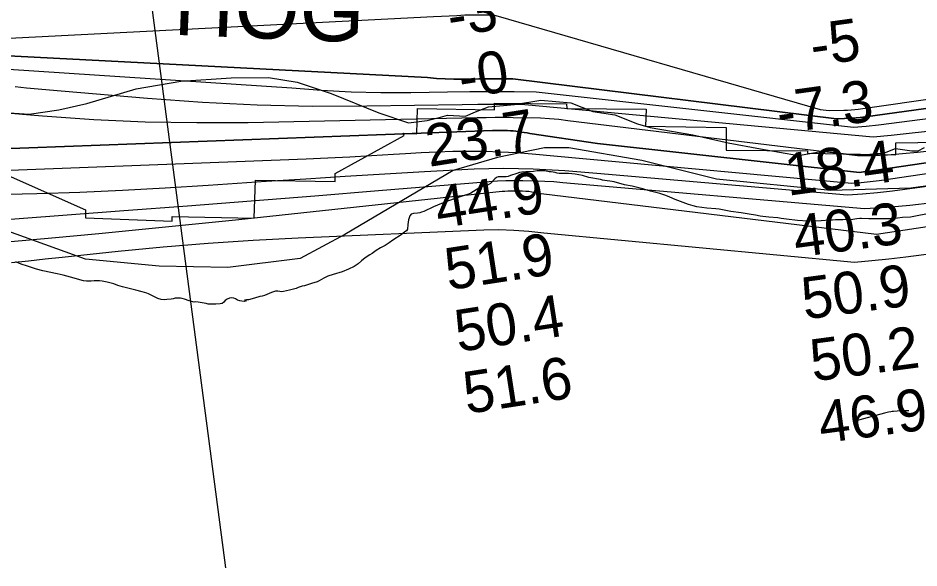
# Model space of a CAD drawing. Extents: x 3192986 to 3230865, y 867483 to 892886.
# Drawn here: x 3202614 to 3204053, y 876187 to 877066 of the extents above; entities that cross this region are included whole.
import ezdxf

# ---------------------------------------------------------------- set-up
doc = ezdxf.new("R2010")
doc.units = 0
for name, color, linetype in [('V-RIVR-EDGE', 7, 'Continuous'), ('V-RIVR-RANG', 7, 'Continuous'), ('V-RRAP-FSHR', 7, 'Continuous'), ('V-RRAP-RVMT', 7, 'Continuous'), ('V-RRAP-RVMT-IDEN', 7, 'Continuous'), ('V-SITE-VEGE', 7, 'Continuous'), ('V-TOPO-DPTH', 7, 'Continuous'), ('V-TOPO-MAJR', 7, 'Continuous'), ('V-TOPO-MINR', 7, 'Continuous'), ('V-TOPO-WATR', 7, 'Continuous')]:
    doc.layers.add(name, color=color, linetype=linetype)

msp = doc.modelspace()

# ---------------------------------------------------------------- linework, layer by layer
at = {"layer": 'V-RIVR-EDGE'}
msp.add_lwpolyline([(3202599.9, 876914.4), (3202631.9, 876912.4), (3202679.1, 876919.4), (3202723.9, 876929.3), (3202802.7, 876953), (3202874.2, 876965.2), (3202954.8, 876970.7), (3203014.5, 876971), (3203060.2, 876963.8), (3203114.1, 876945.5), (3203190.3, 876914.3), (3203237.9, 876898.5), (3203267.5, 876902.2), (3203289, 876907.4), (3203300.4, 876910.7), (3203329, 876909.2), (3203344.8, 876915.9), (3203365.8, 876923.9), (3203407.3, 876928.1), (3203449.3, 876934.7), (3203497, 876930.7), (3203532.2, 876916.8), (3203567.5, 876911.5), (3203603.7, 876897.1), (3203624.2, 876891.3), (3203691.9, 876879.2), (3203748.6, 876866.7), (3203800.1, 876857), (3203861.1, 876846.4), (3203899.7, 876853.5), (3203946, 876848.1), (3203974.6, 876848.5), (3203998.4, 876850.8), (3204015.6, 876857.5), (3204041.8, 876853.6), (3204051.8, 876853.6), (3204062.4, 876859.2)], dxfattribs=at)
at = {"layer": 'V-RIVR-RANG'}
msp.add_line((3202946.1, 876186.9), (3202756, 877634.4), dxfattribs=at)
at = {"layer": 'V-RRAP-FSHR'}
msp.add_lwpolyline([(3204122.5, 876805.2), (3204040.5, 876794), (3203912.8, 876790.2), (3203729.8, 876808.7), (3203610.8, 876838.1), (3203494.1, 876858.4), (3203455.3, 876858.4), (3203380.2, 876842.9), (3203309.4, 876822.1), (3203136.3, 876720), (3203065.1, 876681.8), (3202949.1, 876667.5), (3202839.5, 876669.5), (3202721.9, 876680.7), (3202545.5, 876743.8), (3202438.3, 876819.7), (3202386.2, 876873.5), (3202284.5, 877008.7), (3202190.4, 877075.7), (3202115.3, 877094.8), (3202047.7, 877089.7), (3201993.9, 877081.1), (3201978.5, 877082), (3201950.5, 877081)], dxfattribs=at)
at = {"layer": 'V-RRAP-RVMT'}
for p, q in [((3203375.2, 876919.6), (3203375.1, 876930.1)), ((3203375.1, 876930.1), (3203490.5, 876929)), ((3203490.5, 876929), (3203490.7, 876921.7)), ((3203251.2, 876881.2), (3203252.3, 876921.7)), ((3203252.3, 876921.7), (3203375.2, 876919.6)), ((3203490.7, 876921.7), (3203617.4, 876920.4)), ((3203617.4, 876920.4), (3203616.6, 876893.4)), ((3203616.6, 876893.4), (3203745.5, 876891)), ((3203745.5, 876891), (3203745.2, 876854.8)), ((3203120.8, 876817.4), (3203231.1, 876878.1)), ((3203231.1, 876878.1), (3203229.4, 876881.8)), ((3203229.4, 876881.8), (3203251.2, 876881.2)), ((3204016.2, 876847.6), (3204016.6, 876866.4)), ((3204016.6, 876866.4), (3204144.7, 876868.8)), ((3203745.2, 876854.8), (3203875.5, 876853.8)), ((3203875.5, 876853.8), (3203875.4, 876850.1)), ((3203875.4, 876850.1), (3204016.2, 876847.6)), ((3202598.5, 876814.1), (3202722, 876759.7)), ((3203120.5, 876804.6), (3203120.8, 876817.4)), ((3202991.5, 876746), (3202993.3, 876807.1)), ((3202993.3, 876807.1), (3203120.5, 876804.6)), ((3202722, 876759.7), (3202721.8, 876746.9)), ((3202721.8, 876746.9), (3202860.2, 876741.5)), ((3202860.2, 876741.5), (3202860.5, 876748.9)), ((3202860.5, 876748.9), (3202991.5, 876746))]:
    msp.add_line(p, q, dxfattribs=at)
at = {"layer": 'V-SITE-VEGE'}
for p, q in [((3203397.1, 876813), (3203393.7, 876812.4)), ((3203400.9, 876814.1), (3203397.1, 876813)), ((3203410.8, 876817.7), (3203400.9, 876814.1)), ((3203415.1, 876818.9), (3203410.8, 876817.7)), ((3203419, 876819.7), (3203415.1, 876818.9)), ((3203425.6, 876820.3), (3203419, 876819.7)), ((3203429.3, 876820.3), (3203425.6, 876820.3)), ((3203437.6, 876821), (3203429.3, 876820.3)), ((3203443.2, 876821.9), (3203437.6, 876821)), ((3203451.2, 876822), (3203443.2, 876821.9)), ((3203455.6, 876821.8), (3203451.2, 876822)), ((3203462.7, 876820.4), (3203455.6, 876821.8)), ((3203465.9, 876820.1), (3203462.7, 876820.4)), ((3203469.1, 876819.6), (3203465.9, 876820.1)), ((3203472.3, 876818.9), (3203469.1, 876819.6)), ((3203475.3, 876818), (3203472.3, 876818.9)), ((3203478.5, 876817.6), (3203475.3, 876818)), ((3203482.5, 876817.4), (3203478.5, 876817.6)), ((3203490.4, 876817.8), (3203482.5, 876817.4)), ((3203493.7, 876817.8), (3203490.4, 876817.8)), ((3203504, 876816.7), (3203493.7, 876817.8)), ((3203515.8, 876814.1), (3203504, 876816.7)), ((3203526.2, 876811.2), (3203515.8, 876814.1)), ((3203365.1, 876799.3), (3203361.4, 876798.1)), ((3203368.7, 876801.4), (3203365.1, 876799.3)), ((3203375.7, 876808.9), (3203368.7, 876801.4)), ((3203378.5, 876811), (3203375.7, 876808.9)), ((3203381.4, 876812.1), (3203378.5, 876811)), ((3203385.2, 876812.4), (3203381.4, 876812.1)), ((3203389.5, 876812.2), (3203385.2, 876812.4)), ((3203393.7, 876812.4), (3203389.5, 876812.2)), ((3203544.5, 876807.9), (3203526.2, 876811.2)), ((3203548, 876806.9), (3203544.5, 876807.9)), ((3203551.5, 876806.2), (3203548, 876806.9)), ((3203563.2, 876804.8), (3203551.5, 876806.2)), ((3203566.6, 876804.1), (3203563.2, 876804.8)), ((3203582.8, 876799.6), (3203566.6, 876804.1)), ((3203595, 876797.1), (3203582.8, 876799.6)), ((3203333.7, 876784.5), (3203327, 876782.2)), ((3203337.3, 876786.1), (3203333.7, 876784.5)), ((3203350.1, 876794.3), (3203337.3, 876786.1)), ((3203353.9, 876796.3), (3203350.1, 876794.3)), ((3203361.4, 876798.1), (3203353.9, 876796.3)), ((3203612.3, 876792.8), (3203595, 876797.1)), ((3203616.8, 876791.3), (3203612.3, 876792.8)), ((3203624.5, 876789.2), (3203616.8, 876791.3)), ((3203639.4, 876785.5), (3203624.5, 876789.2)), ((3203649.1, 876782.3), (3203639.4, 876785.5)), ((3203295.8, 876771.6), (3203284.2, 876767.1)), ((3203310.6, 876776.9), (3203295.8, 876771.6)), ((3203320.7, 876780.5), (3203310.6, 876776.9)), ((3203327, 876782.2), (3203320.7, 876780.5)), ((3203655.3, 876779.8), (3203649.1, 876782.3)), ((3203664, 876776), (3203655.3, 876779.8)), ((3203676.4, 876771), (3203664, 876776)), ((3203685.2, 876767.8), (3203676.4, 876771)), ((3203258.9, 876755.5), (3203255.9, 876754.6)), ((3203262.4, 876756.9), (3203258.9, 876755.5)), ((3203277.6, 876764.3), (3203262.4, 876756.9)), ((3203284.2, 876767.1), (3203277.6, 876764.3)), ((3203692.4, 876765.7), (3203685.2, 876767.8)), ((3203698.6, 876764.2), (3203692.4, 876765.7)), ((3203714.7, 876762.2), (3203698.6, 876764.2)), ((3203728.8, 876761.3), (3203714.7, 876762.2)), ((3203734.1, 876760.8), (3203728.8, 876761.3)), ((3203745, 876758.4), (3203734.1, 876760.8)), ((3203752.9, 876757), (3203745, 876758.4)), ((3203769.2, 876754.7), (3203752.9, 876757)), ((3203238, 876743.5), (3203236.7, 876735.8)), ((3203238.8, 876746.7), (3203238, 876743.5)), ((3203240.2, 876749.9), (3203238.8, 876746.7)), ((3203242.2, 876752.4), (3203240.2, 876749.9)), ((3203245.9, 876753.7), (3203242.2, 876752.4)), ((3203252.5, 876754.1), (3203245.9, 876753.7)), ((3203255.9, 876754.6), (3203252.5, 876754.1)), ((3203772.3, 876754.4), (3203769.2, 876754.7)), ((3203778.8, 876753.1), (3203772.3, 876754.4)), ((3203782.1, 876752.8), (3203778.8, 876753.1)), ((3203792, 876751.2), (3203782.1, 876752.8)), ((3203799.6, 876749.5), (3203792, 876751.2)), ((3203803.8, 876748.8), (3203799.6, 876749.5)), ((3203813.6, 876747.7), (3203803.8, 876748.8)), ((3203827.7, 876746.6), (3203813.6, 876747.7)), ((3203833.1, 876745.6), (3203827.7, 876746.6)), ((3203841.9, 876744.7), (3203833.1, 876745.6)), ((3203859.1, 876742.5), (3203841.9, 876744.7)), ((3203875.8, 876741.1), (3203859.1, 876742.5)), ((3203897, 876741.7), (3203875.8, 876741.1)), ((3203910.5, 876743), (3203897, 876741.7)), ((3203915.1, 876743.1), (3203910.5, 876743)), ((3203920, 876743.5), (3203915.1, 876743.1)), ((3203927.1, 876743.7), (3203920, 876743.5)), ((3203931.6, 876743.7), (3203927.1, 876743.7)), ((3203935.2, 876743.9), (3203931.6, 876743.7)), ((3203944.5, 876743.6), (3203935.2, 876743.9)), ((3203953.9, 876744.9), (3203944.5, 876743.6)), ((3203958.8, 876745.4), (3203953.9, 876744.9)), ((3203961.8, 876745.5), (3203958.8, 876745.4)), ((3203973.2, 876745), (3203961.8, 876745.5)), ((3203985, 876745.1), (3203973.2, 876745)), ((3204004.1, 876744.9), (3203985, 876745.1)), ((3204011, 876745.2), (3204004.1, 876744.9)), ((3204027, 876747.1), (3204011, 876745.2)), ((3204039.6, 876748), (3204027, 876747.1)), ((3204048, 876749.3), (3204039.6, 876748)), ((3204067.1, 876753.1), (3204048, 876749.3)), ((3203236.3, 876728.6), (3203234.5, 876726.1)), ((3203236.7, 876735.8), (3203236.3, 876728.6)), ((3203226, 876719.6), (3203212.9, 876711.2)), ((3203231.9, 876724.2), (3203226, 876719.6)), ((3203234.5, 876726.1), (3203231.9, 876724.2)), ((3203193.4, 876698.6), (3203186.4, 876694.2)), ((3203200.4, 876702.6), (3203193.4, 876698.6)), ((3203206.9, 876706.9), (3203200.4, 876702.6)), ((3203212.9, 876711.2), (3203206.9, 876706.9)), ((3203176, 876687.5), (3203168.8, 876682.9)), ((3203179.7, 876689.6), (3203176, 876687.5)), ((3203186.4, 876694.2), (3203179.7, 876689.6)), ((3202616.6, 876673.6), (3202610.8, 876676.2)), ((3202620.8, 876672), (3202616.6, 876673.6)), ((3202627.6, 876670), (3202620.8, 876672)), ((3202635.9, 876667.2), (3202627.6, 876670)), ((3203151, 876669), (3203142.1, 876664.6)), ((3203154.1, 876670.8), (3203151, 876669)), ((3203157.3, 876673.3), (3203154.1, 876670.8)), ((3203162.8, 876678.2), (3203157.3, 876673.3)), ((3203168.8, 876682.9), (3203162.8, 876678.2)), ((3202643.6, 876664.8), (3202635.9, 876667.2)), ((3202654, 876662.1), (3202643.6, 876664.8)), ((3202676.7, 876657.3), (3202654, 876662.1)), ((3202686.1, 876655), (3202676.7, 876657.3)), ((3202697.9, 876651.6), (3202686.1, 876655)), ((3203117.3, 876656.1), (3203109.1, 876653.2)), ((3203131.8, 876660.4), (3203117.3, 876656.1)), ((3203142.1, 876664.6), (3203131.8, 876660.4)), ((3202718.6, 876646.1), (3202697.9, 876651.6)), ((3202723.4, 876645.5), (3202718.6, 876646.1)), ((3202731.1, 876645.5), (3202723.4, 876645.5)), ((3202735.9, 876645.9), (3202731.1, 876645.5)), ((3202744.5, 876645.8), (3202735.9, 876645.9)), ((3202748.7, 876645.6), (3202744.5, 876645.8)), ((3202756.5, 876644), (3202748.7, 876645.6)), ((3202767, 876641), (3202756.5, 876644)), ((3202773.7, 876638.7), (3202767, 876641)), ((3203082.9, 876641.6), (3203071.7, 876638)), ((3203092.1, 876644.6), (3203082.9, 876641.6)), ((3203095, 876645.9), (3203092.1, 876644.6)), ((3203102.4, 876650.1), (3203095, 876645.9)), ((3203105.7, 876651.8), (3203102.4, 876650.1)), ((3203109.1, 876653.2), (3203105.7, 876651.8)), ((3202781.1, 876636.6), (3202773.7, 876638.7)), ((3202802.2, 876631.2), (3202781.1, 876636.6)), ((3202812.6, 876628.4), (3202802.2, 876631.2)), ((3202819.7, 876626.3), (3202812.6, 876628.4)), ((3202822.6, 876625.2), (3202819.7, 876626.3)), ((3203018.8, 876627.3), (3203007.7, 876622.6)), ((3203025.3, 876629.7), (3203018.8, 876627.3)), ((3203029.1, 876629.6), (3203025.3, 876629.7)), ((3203035.3, 876628.4), (3203029.1, 876629.6)), ((3203038.3, 876628.8), (3203035.3, 876628.4)), ((3203047.6, 876631.3), (3203038.3, 876628.8)), ((3203054.3, 876632.6), (3203047.6, 876631.3)), ((3203058.3, 876633.9), (3203054.3, 876632.6)), ((3203061.4, 876635.3), (3203058.3, 876633.9)), ((3203065, 876636.5), (3203061.4, 876635.3)), ((3203068.3, 876637.4), (3203065, 876636.5)), ((3203071.7, 876638), (3203068.3, 876637.4)), ((3202831.9, 876620.5), (3202822.6, 876625.2)), ((3202837.5, 876617.9), (3202831.9, 876620.5)), ((3202842.7, 876616.2), (3202837.5, 876617.9)), ((3202847.7, 876615.6), (3202842.7, 876616.2)), ((3202851.7, 876615.9), (3202847.7, 876615.6)), ((3202859, 876616.7), (3202851.7, 876615.9)), ((3202862.1, 876617.2), (3202859, 876616.7)), ((3202865, 876618), (3202862.1, 876617.2)), ((3202868.5, 876618.3), (3202865, 876618)), ((3202873.6, 876618.2), (3202868.5, 876618.3)), ((3202876.6, 876617.6), (3202873.6, 876618.2)), ((3202880.3, 876616.7), (3202876.6, 876617.6)), ((3202887.6, 876614), (3202880.3, 876616.7)), ((3202895.3, 876611.8), (3202887.6, 876614)), ((3202898.4, 876612.2), (3202895.3, 876611.8)), ((3202901.9, 876612.1), (3202898.4, 876612.2)), ((3202914.5, 876609.6), (3202901.9, 876612.1)), ((3202942.7, 876612), (3202940, 876609.8)), ((3202945.1, 876614.5), (3202942.7, 876612)), ((3202948.4, 876616.4), (3202945.1, 876614.5)), ((3202951.8, 876618), (3202948.4, 876616.4)), ((3202955.1, 876618.7), (3202951.8, 876618)), ((3202958.8, 876618.3), (3202955.1, 876618.7)), ((3202961.8, 876617.1), (3202958.8, 876618.3)), ((3202964.9, 876615.3), (3202961.8, 876617.1)), ((3202968.4, 876613.9), (3202964.9, 876615.3)), ((3202971.6, 876613.2), (3202968.4, 876613.9)), ((3202975.5, 876613), (3202971.6, 876613.2)), ((3202978.8, 876613.8), (3202975.5, 876613)), ((3202979.3, 876615.5), (3202975.9, 876614.8)), ((3202975.9, 876614.8), (3202978.8, 876613.8)), ((3202982.4, 876615.7), (3202979.3, 876615.5)), ((3202992, 876618.2), (3202982.4, 876615.7)), ((3203000.4, 876620.8), (3202992, 876618.2)), ((3203004.3, 876621.4), (3203000.4, 876620.8)), ((3203007.7, 876622.6), (3203004.3, 876621.4)), ((3202918.1, 876608.9), (3202914.5, 876609.6)), ((3202921.6, 876608.5), (3202918.1, 876608.9)), ((3202930.1, 876608.6), (3202921.6, 876608.5)), ((3202936.9, 876609), (3202930.1, 876608.6)), ((3202940, 876609.8), (3202936.9, 876609))]:
    msp.add_line(p, q, dxfattribs=at)
at = {"layer": 'V-TOPO-DPTH'}
for points in [[(3204976.4, 877047.2), (3203971.8, 876908.7), (3203959.3, 876907.2), (3203946.8, 876906.1), (3203934.3, 876905.4), (3203921.7, 876905.1), (3203404.5, 876968.9), (3203386.5, 876969), (3203368.5, 876969), (3203350.5, 876968.8), (3203332.4, 876968.5), (3203324.5, 876968.4), (3203310.4, 876968.3), (3203296.4, 876968.7), (3203282.5, 876969.6), (3203268.5, 876970.9), (3202515.6, 877010.2)], [(3204805.9, 877023.7), (3203971.8, 876908.7), (3203959.3, 876907.2), (3203946.8, 876906.1), (3203934.3, 876905.4), (3203921.7, 876905.1), (3203404.5, 876968.9), (3203386.5, 876969), (3203368.5, 876969), (3203350.5, 876968.8), (3203332.4, 876968.5), (3203324.5, 876968.4), (3203310.4, 876968.3), (3203296.4, 876968.7), (3203282.5, 876969.6), (3203268.5, 876970.9), (3202515.6, 877010.2)], [(3202609.4, 876956.5), (3202627.8, 876954.7), (3202646.2, 876953), (3202664.6, 876951.3), (3202683, 876949.7), (3202821.1, 876937.8), (3202908.6, 876931.6), (3202996.2, 876927.1), (3203083.8, 876925.4), (3203171.5, 876925.5), (3203323.8, 876927.9), (3203348.8, 876928.2), (3203373.8, 876928.3), (3203398.8, 876928.2), (3203423.8, 876927.9), (3203980.3, 876876.3), (3204009.2, 876878.9), (3204172.8, 876896.8)], [(3202609.4, 876956.5), (3202627.8, 876954.7), (3202646.2, 876953), (3202664.6, 876951.3), (3202683, 876949.7), (3202821.1, 876937.8), (3202908.6, 876931.6), (3202996.2, 876927.1), (3203083.8, 876925.4), (3203171.5, 876925.5), (3203323.8, 876927.9), (3203348.8, 876928.2), (3203373.8, 876928.3), (3203398.8, 876928.2), (3203423.8, 876927.9), (3203980.3, 876876.3), (3204009.2, 876878.9), (3204172.8, 876896.8)], [(3204278.3, 876866.2), (3203970.6, 876820.8), (3203964.6, 876820.1), (3203958.6, 876819.4), (3203539.6, 876865.3), (3203431.7, 876881.7), (3203427.3, 876882.4), (3203422.8, 876883), (3203418.4, 876883.8), (3203413.9, 876884.5), (3203409.5, 876885.1), (3203405, 876885.6), (3203400.6, 876885.9), (3203396.1, 876886.1), (3203386.6, 876886.3), (3203383, 876886.3), (3203379.3, 876886.3), (3203375.6, 876886.3), (3203371.9, 876886.2), (3202573.8, 876856.3)]]:
    msp.add_lwpolyline(points, dxfattribs=at)
at = {"layer": 'V-TOPO-MAJR'}
msp.add_lwpolyline([(3202525, 876738.9), (3202782.9, 876758.2), (3202884.7, 876766), (3202986.5, 876773.9), (3203088.3, 876782), (3203190, 876790.3), (3203366.8, 876805), (3203380.2, 876805.9), (3203393.5, 876806.4), (3203406.9, 876806.6), (3203420.3, 876806.4), (3203455.6, 876805.3), (3203470, 876804.6), (3203484.5, 876803.3), (3203966.6, 876761.4), (3204002.7, 876763.9), (3204038.8, 876767.2), (3204112.1, 876775.2)], dxfattribs=at)
at = {"layer": 'V-TOPO-MINR'}
for points in [[(3202495.4, 877028.5), (3203278.1, 877068.6), (3203290.5, 877069.2), (3203302.9, 877069.8), (3203315.3, 877070.4), (3203327.7, 877071), (3203340.2, 877071.4), (3203352.6, 877071.4), (3203365, 877071.1), (3203377.3, 877070.4), (3203895.5, 876920.1), (3203900.2, 876919.1), (3203905, 876918.6), (3203909.8, 876918.4), (3203933.5, 876918.7), (3203939.3, 876918.9), (3203945, 876919.2), (3203950.7, 876919.8), (3203956.4, 876920.5), (3204375.6, 876980.7)], [(3202515.6, 877010.2), (3203268.5, 876970.9), (3203282.5, 876969.6), (3203296.4, 876968.7), (3203310.4, 876968.3), (3203324.5, 876968.4), (3203332.4, 876968.5), (3203350.5, 876968.8), (3203368.5, 876969), (3203386.5, 876969), (3203404.5, 876968.9), (3203921.7, 876905.1), (3203934.3, 876905.4), (3203946.8, 876906.1), (3203959.3, 876907.2), (3203971.8, 876908.7), (3204976.4, 877047.2)], [(3202509.7, 876990.2), (3203051.4, 876954.5), (3203098.8, 876950.7), (3203146.3, 876948), (3203193.9, 876946.9), (3203241.5, 876947), (3203300.4, 876948), (3203335.7, 876948.5), (3203371.1, 876948.7), (3203406.5, 876948.7), (3203441.8, 876948.3), (3203948.8, 876891.6), (3203968.8, 876893.3), (3203988.8, 876895.5), (3204472.4, 876957.5)], [(3202530.6, 876820.2), (3203074.3, 876841), (3203109.2, 876842.5), (3203144.1, 876844.2), (3203178.9, 876846.2), (3203213.8, 876848.5), (3203232.9, 876849.8), (3203258.2, 876851.2), (3203283.5, 876852.4), (3203308.9, 876853.1), (3203334.2, 876853.4), (3203359.6, 876853.2), (3203384.9, 876852.4), (3203410.2, 876850.9), (3203435.4, 876849), (3203516.4, 876841.5), (3203946.3, 876802.2), (3203960.8, 876803.2), (3203975.2, 876804.7), (3203989.6, 876806.6), (3205150.3, 876977.2)], [(3202513.3, 876921.3), (3202653.3, 876909.6), (3202735.4, 876904), (3202817.5, 876900.1), (3202899.6, 876898.9), (3202981.8, 876899.3), (3203347.7, 876907.1), (3203362.1, 876907.3), (3203376.5, 876907.4), (3203390.9, 876907.4), (3203405.3, 876907.2), (3203448.6, 876906.4), (3203463.3, 876905.7), (3203477.9, 876904.4), (3203492.5, 876902.3), (3203955.1, 876846.2), (3203979.1, 876846.6), (3204003.1, 876847.6), (3204027.1, 876849.4), (3204051, 876851.6), (3204074.9, 876854.4)], [(3202573.8, 876856.3), (3203371.9, 876886.2), (3203375.6, 876886.3), (3203379.3, 876886.3), (3203383, 876886.3), (3203386.6, 876886.3), (3203396.1, 876886.1), (3203400.6, 876885.9), (3203405, 876885.6), (3203409.5, 876885.1), (3203413.9, 876884.5), (3203418.4, 876883.8), (3203422.8, 876883), (3203427.3, 876882.4), (3203431.7, 876881.7), (3203539.6, 876865.3), (3203958.6, 876819.4), (3203964.6, 876820.1), (3203970.6, 876820.8), (3204278.3, 876866.2)], [(3202573.8, 876783.8), (3202644.3, 876785.7), (3202712.7, 876787.9), (3202781.1, 876790.7), (3202849.4, 876794.4), (3202917.7, 876798.7), (3203010.6, 876805.1), (3203073.8, 876809.3), (3203136.9, 876813.3), (3203200.1, 876817.1), (3203263.4, 876820.6), (3203342.6, 876824.8), (3203366.2, 876825.7), (3203389.8, 876826), (3203413.4, 876825.7), (3203437, 876824.8), (3203487.9, 876822.1), (3203513.4, 876820.3), (3203538.9, 876818), (3203939.4, 876783.4), (3203963.3, 876784.9), (3203987.2, 876787.1), (3204011.1, 876789.9), (3204425.5, 876845.8)], [(3202566.5, 876705.7), (3202668.4, 876714.8), (3202743.1, 876721.7), (3202817.8, 876728.9), (3202892.5, 876736.4), (3202967.1, 876744.2), (3203387.3, 876789.1), (3203392, 876789.5), (3203396.7, 876789.8), (3203401.3, 876789.9), (3203406, 876789.9), (3203420.2, 876789.7), (3203425.2, 876789.5), (3203430.1, 876789.1), (3203435, 876788.4), (3203439.9, 876787.5), (3203444.8, 876786.5), (3203449.6, 876785.4), (3203985.5, 876720.7), (3204267.4, 876763.4)], [(3202603.9, 876675.4), (3202630.8, 876678.1), (3202657.7, 876680.9), (3202684.6, 876683.7), (3202774.3, 876693.3), (3202846, 876700.3), (3202917.9, 876706.4), (3202989.8, 876711), (3203061.9, 876714.8), (3203358.5, 876727.4), (3203382.4, 876727.8), (3203406.3, 876727.2), (3203430.2, 876725.4), (3203453.9, 876722.7), (3203950.3, 876675.9), (3203977.8, 876678.3), (3204005.2, 876681.2), (3204032.5, 876684.5), (3204275.8, 876715.8)], [(3204037, 876438.2), (3204032.8, 876438.3), (3204030.7, 876438.3), (3204026.5, 876438.2), (3204024.4, 876438.1), (3204012.7, 876437.1), (3204010.6, 876436.9), (3204008.4, 876436.6), (3204004.5, 876435.9), (3204000.5, 876435), (3203998.5, 876434.5), (3203950.7, 876421.7)]]:
    msp.add_lwpolyline(points, dxfattribs=at)
at = {"layer": 'V-TOPO-WATR'}
msp.add_lwpolyline([(3202609.4, 876956.5), (3202627.8, 876954.7), (3202646.2, 876953), (3202664.6, 876951.3), (3202683, 876949.7), (3202821.1, 876937.8), (3202908.6, 876931.6), (3202996.2, 876927.1), (3203083.8, 876925.4), (3203171.5, 876925.5), (3203323.8, 876927.9), (3203348.8, 876928.2), (3203373.8, 876928.3), (3203398.8, 876928.2), (3203423.8, 876927.9), (3203980.3, 876876.3), (3204009.2, 876878.9), (3204172.8, 876896.8)], dxfattribs=at)

# ---------------------------------------------------------------- texts
at = {"layer": 'V-RIVR-RANG'}
for s, rotation, p in [('-3', 8.9337, (3203305.1, 877036)), ('-5', 7.8253, (3203884.1, 876989.2)), ('-0', 8.9337, (3203323, 876937.5)), ('-7.3', 7.8253, (3203830.4, 876880.9)), ('23.7', 8.9337, (3203270.8, 876828.1)), ('18.4', 7.8253, (3203843.9, 876781.8)), ('44.9', 8.7883, (3203285.9, 876729.6)), ('40.3', 7.5983, (3203857.2, 876683.2)), ('51.9', 8.7883, (3203301.4, 876630.8)), ('50.9', 7.5983, (3203870.4, 876584)), ('50.4', 8.7883, (3203317.2, 876532)), ('50.2', 7.5983, (3203884.1, 876485)), ('51.6', 8.7883, (3203330.9, 876433)), ('46.9', 7.5983, (3203897.3, 876385.9))]:
    msp.add_text(s, height=67, rotation=rotation, dxfattribs=at).set_placement(p)
at = {"layer": 'V-RRAP-RVMT-IDEN'}
msp.add_text('HOG', height=100, rotation=357.6513, dxfattribs=at).set_placement((3202861.7, 877039.4))

doc.saveas('drawing.dxf')
